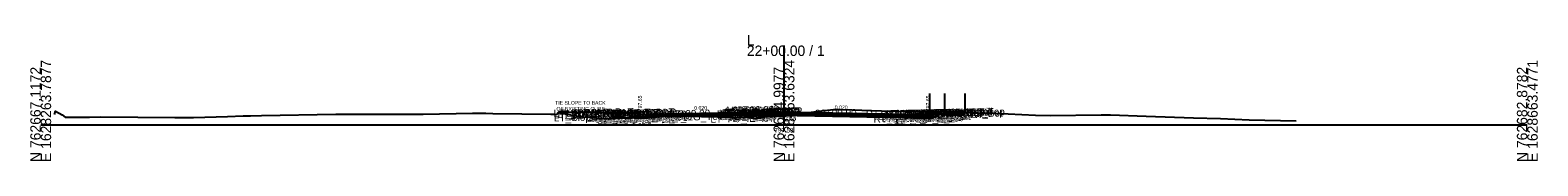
# Model space of a CAD drawing. Extents: x -26 to 4403, y -510 to 9556.
# Drawn here: x 997.2 to 1402.8, y 1990.3 to 2024.1 of the extents above; entities that cross this region are included whole.
import ezdxf

# ---------------------------------------------------------------- set-up
doc = ezdxf.new("R2010")
doc.units = 0
for name, color, linetype in [('Default', 7, 'Continuous'), ('Exist CMT Pavement', 7, 'Continuous'), ('Exist Cross Section Cell', 7, 'Continuous'), ('Exist XS Center Line Elevation Label', 7, 'Continuous'), ('Exist XS Ground Line', 7, 'Continuous'), ('Prop CMT Conc Surface', 7, 'Continuous'), ('Prop CMT Concrete Structures', 7, 'Continuous'), ('Prop CMT Pvmt Course 1', 7, 'Continuous'), ('Prop CMT Pvmt Course 1 CG', 7, 'Continuous'), ('Prop CMT Pvmt Course 1 Wedge', 7, 'Continuous'), ('Prop CMT Pvmt Course 2', 7, 'Continuous'), ('Prop CMT Pvmt Course 2 Wedge', 7, 'Continuous'), ('Prop CMT Pvmt Course 3', 7, 'Continuous'), ('Prop CMT Pvmt Course 3 Wedge', 7, 'Continuous'), ('Prop CMT Pvmt Surface', 7, 'Continuous'), ('Prop CMT Pvmt Wedge Surface 1', 7, 'Continuous'), ('Prop CMT Pvmt Wedge Surface 2', 7, 'Continuous'), ('Prop CMT Pvmt Wedge Surface 3', 7, 'Continuous'), ('Prop CMT Slope Grass', 7, 'Continuous'), ('Prop CMT Subgrade Earthwork', 7, 'Continuous'), ('Prop XS Finish Grade Concrete', 7, 'Continuous'), ('Prop XS Hydro Elevations', 7, 'Continuous'), ('Prop XS SE Text', 7, 'Continuous'), ('Prop XS Side Slope Text', 7, 'Continuous'), ('Scratch_Level_0', 7, 'Continuous'), ('Scratch_Level_1', 7, 'Continuous')]:
    doc.layers.add(name, color=color, linetype=linetype)

msp = doc.modelspace()

# ---------------------------------------------------------------- linework, layer by layer
at = {"layer": 'Exist CMT Pavement'}
msp.add_lwpolyline([(1163.27, 2002.1), (1168.97, 2002.29), (1171.48, 2002.37), (1173.53, 2002.32), (1190.76, 2001.93)], dxfattribs=at)
at = {"layer": 'Exist Cross Section Cell'}
for p, q in [((1200, 2000), (1200, 2021.33)), ((1000, 2000), (1200, 2000)), ((1200, 2000), (1400, 2000))]:
    msp.add_line(p, q, dxfattribs=at)
at = {"layer": 'Exist XS Ground Line'}
msp.add_lwpolyline([(1003.68, 2002.75), (1004, 2003.65), (1005.81, 2002.72), (1006.56, 2002.04), (1013.13, 2002.08), (1016.2, 2002.14), (1036.1, 2001.95), (1040.29, 2001.94), (1041.07, 2001.94), (1050.25, 2002.25), (1054.46, 2002.39), (1055.76, 2002.44), (1056.45, 2002.46), (1059.44, 2002.54), (1079.39, 2002.84), (1083.51, 2002.89), (1099.19, 2002.85), (1101.25, 2002.86), (1101.58, 2002.86), (1102.93, 2002.88), (1116.16, 2003.15), (1119.78, 2003.14), (1121.67, 2003.05), (1137.24, 2002.87), (1138.25, 2002.84), (1138.74, 2002.82), (1139.24, 2003.32), (1142.57, 2002.73), (1145.78, 2002.12), (1148.69, 2002.09), (1149.14, 2002.09), (1149.64, 2001.64), (1168.97, 2002.29), (1171.48, 2002.37), (1173.53, 2002.32), (1190.76, 2001.93), (1191.17, 2001.89), (1192.59, 2001.74), (1193.27, 2002.18), (1196.89, 2002.29), (1197.54, 2002.31), (1198.02, 2002.33), (1199.37, 2002.45), (1200, 2002.53), (1210.93, 2003.83), (1213.33, 2004.1), (1214.81, 2004.1), (1218.26, 2004), (1226.21, 2003.75), (1230.01, 2003.72), (1236.95, 2003.61), (1239.78, 2003.61), (1244.85, 2003.57), (1250.98, 2003.27), (1256.68, 2003.1), (1267.66, 2002.57), (1271.63, 2002.55), (1285.38, 2002.73), (1287.86, 2002.73), (1297.47, 2002.31), (1310.18, 2001.86), (1317.48, 2001.68), (1325.18, 2001.35), (1337.84, 2001.06)], dxfattribs=at)
at = {"layer": 'Prop CMT Conc Surface'}
for points in [[(1156.75, 2003.24), (1151.75, 2003.34)], [(1161.25, 2002.65), (1161.25, 2003.14), (1160.75, 2003.14)], [(1163.25, 2002.77), (1161.25, 2002.65)]]:
    msp.add_lwpolyline(points, dxfattribs=at)
at = {"layer": 'Prop CMT Concrete Structures'}
for p, q in [((1239.25, 2002.83), (1243.25, 2002.99)), ((1243.25, 2002.99), (1248.75, 2003.1)), ((1252.2, 2003.23), (1248.75, 2003.1))]:
    msp.add_line(p, q, dxfattribs=at)
for points in [[(1151.75, 2003), (1151.75, 2003.34)], [(1151.75, 2003.34), (1156.75, 2003.24)], [(1156.75, 2002.9), (1151.75, 2003)], [(1156.75, 2003.24), (1156.75, 2002.9)], [(1163.25, 2002.77), (1161.25, 2002.65), (1161.25, 2003.14), (1160.75, 2003.14)], [(1160.75, 2003.14), (1160.75, 2002.13), (1163.25, 2002.18)], [(1163.25, 2002.18), (1163.25, 2002.77)], [(1194, 2003.62), (1193.99, 2003.79), (1192.76, 2003.76), (1192.76, 2003.76), (1192.01, 2003.51), (1192, 2003.34)], [(1192, 2003.34), (1194, 2003.62)], [(1239.25, 2002.83), (1239.25, 2002.13), (1236.75, 2002.18)], [(1236.75, 2002.18), (1236.75, 2002.77)], [(1236.75, 2002.77), (1238.5, 2002.66)], [(1236.75, 2002.18), (1236.75, 2002.77)], [(1243.25, 2002.99), (1243.25, 2002.65)], [(1243.25, 2002.65), (1248.25, 2002.75)], [(1248.25, 2002.75), (1248.25, 2003.09)]]:
    msp.add_lwpolyline(points, dxfattribs=at)
at = {"layer": 'Prop CMT Pvmt Course 1'}
for points in [[(1192, 2003.34), (1163.25, 2002.77)], [(1163.25, 2002.64), (1192, 2003.21)], [(1163.25, 2002.77), (1163.25, 2002.52), (1163.25, 2002.52), (1163.25, 2002.64)], [(1192, 2003.34), (1194, 2003.62)], [(1194, 2003.37), (1192, 2003.09)], [(1192, 2003.09), (1192, 2003.34)], [(1192, 2003.09), (1192, 2003.34)], [(1192, 2003.21), (1192, 2003.09), (1192, 2003.09)], [(1194, 2003.62), (1194, 2003.37)], [(1194, 2003.62), (1236.75, 2002.77)], [(1194, 2003.37), (1194, 2003.62)], [(1236.75, 2002.52), (1194, 2003.37)], [(1194, 2003.37), (1194, 2003.37)], [(1236.75, 2002.77), (1236.75, 2002.52)]]:
    msp.add_lwpolyline(points, dxfattribs=at)
msp.add_lwpolyline([(1194, 2003.37), (1194, 2003.49), (1194, 2003.49)], close=True, dxfattribs=at)
at = {"layer": 'Prop CMT Pvmt Course 1 CG'}
for points in [[(1163.25, 2002.18), (1160.25, 2002.12), (1159.91, 2001.78)], [(1159.91, 2001.78), (1163.25, 2001.85)], [(1163.25, 2001.85), (1163.25, 2002.18)], [(1236.75, 2002.18), (1239.75, 2002.12), (1240.09, 2001.78)], [(1236.75, 2001.85), (1236.75, 2002.18)], [(1240.09, 2001.78), (1236.75, 2001.85)]]:
    msp.add_lwpolyline(points, dxfattribs=at)
at = {"layer": 'Prop CMT Pvmt Course 1 Wedge'}
for points in [[(1163.25, 2002.64), (1168.97, 2002.75), (1171.48, 2002.8), (1173.53, 2002.85), (1190.76, 2003.19), (1191.17, 2003.2), (1192, 2003.21)], [(1192, 2003.09), (1191.17, 2003.07), (1190.76, 2003.07), (1173.53, 2002.72), (1171.48, 2002.68), (1168.97, 2002.63), (1163.25, 2002.52)], [(1163.25, 2002.52), (1163.25, 2002.64)], [(1192, 2003.21), (1192, 2003.09)]]:
    msp.add_lwpolyline(points, dxfattribs=at)
at = {"layer": 'Prop CMT Pvmt Course 2'}
for points in [[(1163.25, 2002.18), (1163.25, 2002.18), (1163.25, 2002.52), (1163.25, 2002.52)], [(1163.25, 2002.52), (1163.25, 2002.18)], [(1192, 2003.09), (1194, 2003.37)], [(1192, 2002.76), (1192, 2003.09)], [(1194, 2003.04), (1192, 2002.76)], [(1194, 2003.37), (1194, 2003.04)], [(1194, 2003.04), (1194, 2003.37)], [(1194, 2003.37), (1236.75, 2002.52)], [(1236.75, 2002.18), (1194, 2003.04)], [(1236.75, 2002.52), (1236.75, 2002.18)]]:
    msp.add_lwpolyline(points, dxfattribs=at)
at = {"layer": 'Prop CMT Pvmt Course 2 Wedge'}
for points in [[(1163.25, 2002.52), (1168.97, 2002.63), (1171.48, 2002.68), (1173.53, 2002.72), (1190.76, 2003.07), (1191.17, 2003.07), (1192, 2003.09)], [(1192, 2002.76), (1191.17, 2002.74), (1190.76, 2002.73), (1173.53, 2002.39), (1172.1, 2002.36), (1171.48, 2002.37), (1169.69, 2002.31), (1168.97, 2002.3), (1163.25, 2002.18)], [(1163.25, 2002.18), (1163.25, 2002.52)], [(1192, 2003.09), (1192, 2002.76)]]:
    msp.add_lwpolyline(points, dxfattribs=at)
at = {"layer": 'Prop CMT Pvmt Course 3'}
for points in [[(1163.25, 2002.18), (1163.25, 2002.18), (1163.25, 2001.85), (1163.25, 2001.85)], [(1163.25, 2001.85), (1163.25, 2002.18)], [(1192, 2002.76), (1194, 2003.04)], [(1192, 2002.42), (1192, 2002.76)], [(1194, 2002.7), (1192, 2002.42)], [(1194, 2003.04), (1194, 2002.7)], [(1194, 2003.04), (1236.75, 2002.18)], [(1194, 2002.7), (1194, 2003.04)], [(1236.75, 2001.85), (1194, 2002.7)], [(1236.75, 2002.18), (1236.75, 2001.85)]]:
    msp.add_lwpolyline(points, dxfattribs=at)
at = {"layer": 'Prop CMT Pvmt Course 3 Wedge'}
for points in [[(1163.25, 2002.18), (1168.97, 2002.3), (1169.71, 2002.31)], [(1169.71, 2002.31), (1168.97, 2002.29), (1163.25, 2002.1)], [(1163.25, 2002.1), (1163.25, 2002.18)], [(1172.09, 2002.36), (1173.53, 2002.39)], [(1192, 2001.8), (1191.17, 2001.89), (1190.76, 2001.93), (1173.53, 2002.32), (1172.09, 2002.36)], [(1173.53, 2002.39), (1190.76, 2002.73), (1191.17, 2002.74), (1192, 2002.76)]]:
    msp.add_lwpolyline(points, dxfattribs=at)
at = {"layer": 'Prop CMT Pvmt Surface'}
for points in [[(1192, 2003.34), (1163.25, 2002.77)], [(1192, 2003.34), (1194, 2003.62)], [(1194, 2003.62), (1236.75, 2002.77)]]:
    msp.add_lwpolyline(points, dxfattribs=at)
at = {"layer": 'Prop CMT Pvmt Wedge Surface 1'}
for points in [[(1192, 2003.21), (1163.25, 2002.64)], [(1163.25, 2002.52), (1163.25, 2002.77)], [(1163.25, 2002.64), (1163.25, 2002.52), (1163.25, 2002.52)], [(1192, 2003.34), (1192, 2003.09), (1192, 2003.09), (1192, 2003.21)]]:
    msp.add_lwpolyline(points, dxfattribs=at)
at = {"layer": 'Prop CMT Pvmt Wedge Surface 2'}
for points in [[(1192, 2003.09), (1163.25, 2002.52)], [(1163.25, 2002.52), (1163.25, 2002.77)], [(1192, 2003.34), (1192, 2003.09)]]:
    msp.add_lwpolyline(points, dxfattribs=at)
at = {"layer": 'Prop CMT Pvmt Wedge Surface 3'}
for points in [[(1163.25, 2002.18), (1163.25, 2002.77)], [(1192, 2002.76), (1163.25, 2002.18)], [(1192, 2003.34), (1192, 2002.76)]]:
    msp.add_lwpolyline(points, dxfattribs=at)
at = {"layer": 'Prop CMT Slope Grass'}
msp.add_lwpolyline([(1160.75, 2003.14), (1151.25, 2003.34), (1139.24, 2003.32)], dxfattribs=at)
at = {"layer": 'Prop CMT Subgrade Earthwork'}
msp.add_line((1190.76, 2002.4), (1190.76, 2001.93), dxfattribs=at)
for points in [[(1163.25, 2001.85), (1159.91, 2001.78), (1158.5, 2003.19)], [(1163.25, 2001.85), (1163.27, 2002.1)], [(1163.25, 2001.85), (1163.25, 2001.85)], [(1192, 2002.42), (1191.17, 2002.41), (1190.76, 2002.4)], [(1192, 2002.42), (1194, 2002.7)], [(1194, 2002.7), (1236.75, 2001.85)], [(1236.75, 2001.85), (1240.09, 2001.78), (1241.21, 2002.91)]]:
    msp.add_lwpolyline(points, dxfattribs=at)
at = {"layer": 'Prop XS Finish Grade Concrete'}
msp.add_line((1238.5, 2002.66), (1239.25, 2002.83), dxfattribs=at)
at = {"layer": 'Scratch_Level_1'}
for p, q in [((1239.25, 2002.83), (1239.25, 2008.47)), ((1243.25, 2002.99), (1243.25, 2008.47)), ((1248.75, 2003.1), (1248.75, 2008.47))]:
    msp.add_line(p, q, dxfattribs=at)

# ---------------------------------------------------------------- texts
at = {"layer": 'Default'}
msp.add_text('-', height=0.0001, dxfattribs=at).set_placement((1000, 2000))
at = {"layer": 'Exist Cross Section Cell'}
for s, p in [('22+00.00 / 1', (1190, 2018.53)), ('L', (1190, 2021.33))]:
    msp.add_text(s, height=2.8, dxfattribs=at).set_placement(p)
for s, p in [('E 1628263.7877', (1002.8, 1990)), ('E 1628463.6324', (1202.8, 1990)), ('E 1628663.4771', (1402.8, 1990)), ('N 762667.1172', (1000, 1990)), ('N 762674.9977', (1200, 1990)), ('N 762682.8782', (1400, 1990))]:
    msp.add_text(s, height=2.8, rotation=90, dxfattribs=at).set_placement(p)
at = {"layer": 'Exist XS Center Line Elevation Label'}
msp.add_text('797.53', height=1.2, dxfattribs=at).set_placement((1197.46, 1997.93))
at = {"layer": 'Prop XS Hydro Elevations'}
for p in [(1161.75, 2003.65), (1239.25, 2003.65)]:
    msp.add_text('797.65', height=1, rotation=90, dxfattribs=at).set_placement(p)
at = {"layer": 'Prop XS SE Text'}
for s, rotation, p in [('0.020', 1.1457, (1175.86, 2004.02)), ('0.020', 358.8543, (1213.65, 2004.23)), ('4.00%', 2.2906, (1239.43, 2003.15)), ('2.00%', 1.1458, (1244.19, 2003.19)), ('4.00%', 2.2906, (1249.04, 2003.32))]:
    msp.add_text(s, height=1, rotation=rotation, dxfattribs=at).set_placement(p)
at = {"layer": 'Prop XS Side Slope Text'}
for s, p in [('TIE SLOPE TO BACK', (1138.42, 2005.42)), ('OF EXISTING CURB', (1138.78, 2003.79))]:
    msp.add_text(s, height=1, dxfattribs=at).set_placement(p)
at = {"layer": 'Scratch_Level_0'}
for s, p in [('LT_SDWK_Out_Top', (1138.01, 2002.06)), ('LT_SDWK_Out_Bot', (1138.04, 2001.73)), ('LT_Sub_Trench_Out_DLT', (1139.09, 2001.8)), ('LT_CSLP_Pnt', (1141.44, 2002.14)), ('LT_SDWK_In_Top', (1144.63, 2001.99)), ('LT_CG_Top_Face', (1148.53, 2001.89)), ('LT_CG_Top_BOC', (1149.05, 2001.91)), ('22+00.00', (1153.57, 2002.02)), ('22+00.00', (1154.1, 2002.01)), ('22+00.00', (1168.94, 2001.88)), ('LT_PV2_IEEOP', (1181.98, 2001.89)), ('LT_PV1_IEEOP', (1182.54, 2002.03)), ('LT_PV2_PGL1', (1182.9, 2001.91)), ('LT_PV2_PGL', (1183.23, 2001.91)), ('RT_PV2_OEEOP', (1183.28, 2002.16)), ('RT_PV3_OEEOP', (1183.28, 2001.82)), ('LT_PV1_PGL', (1183.8, 2002.18)), ('RT_PV1_OEEOP', (1183.85, 2002.29)), ('MI_Face In', (1183.92, 2002.35)), ('RT_PV2_IEEOP', (1183.93, 2002.17)), ('MI_Face Out', (1184.28, 2002.59)), ('MI_Top Out', (1184.49, 2002.86)), ('RT_PV1_IEEOP', (1184.49, 2002.3)), ('RT_PV2_PGL1', (1184.86, 2002.19)), ('RT_PV3_PGL1', (1184.86, 2001.85)), ('22+00.00', (1185.19, 2002.33)), ('RT_PV2_PGL', (1185.19, 2002.19)), ('MI_Bot Out', (1185.28, 2002.45)), ('22+00.00', (1185.38, 2002.43)), ('MI_Top In', (1185.63, 2002.61)), ('RT_PV1_PGL', (1185.75, 2002.45)), ('22+00.00', (1186.13, 2002.83)), ('MI_Crown', (1186.09, 2002.9)), ('22+00.00', (1186.26, 2002.9)), ('22+00.00', (1186.96, 2002.72)), ('22+00.00', (1187.18, 2002.59)), ('22+00.00', (1208.33, 2002.06)), ('RT_Sub_Trench_Out_DLT', (1222.04, 2001.8)), ('RT_CG_Top_Face', (1225.99, 2001.89)), ('RT_CG_Top_BOC', (1227.51, 2001.91)), ('RT_SDWK_In_Top', (1231.08, 2001.99)), ('22+00.00', (1232.24, 2002.01)), ('22+00.00', (1233.87, 2002.04)), ('RT_SDWK_Out_Top', (1234.46, 2002.06)), ('RT_SDWK_Out_Bot', (1234.49, 2001.73)), ('RT_Slope_Cut', (1238.48, 2002.17)), ('RT_Slope_Fill', (1239.36, 2002.18)), ('RT_Shld_O', (1240.81, 2002.18)), ('CSLP_Pnt', (1241.64, 2002.19)), ('22+00.00', (1242.01, 2002.22)), ('LT_Slope_Fill', (1138.1, 2000.91)), ('22+00.00', (1142.56, 2001.57)), ('LT_SDWK_In_Bot', (1144.66, 2001.66)), ('LT_CG1_Shelf_Out', (1146.82, 2000.85)), ('LT_PV_Sub_Tie_Out', (1148.23, 2000.8)), ('LT_CG_Bot_BOC', (1149.09, 2000.9)), ('LT_CG_Top_Gut', (1149.51, 2001.41)), ('LT_Sub_OEOP', (1150.04, 2000.58)), ('LT_Sub_OEOT_CG', (1150.64, 2000.6)), ('LT_PV_OEEOP_EG', (1150.82, 2000.85)), ('LT_Sub_OEEOP', (1152.48, 2000.63)), ('LT_PV2_OEEOP', (1152.58, 2001.3)), ('LT_PV3_OEEOP', (1152.58, 2000.97)), ('LT_PV1_OEEOP', (1153.15, 2001.44)), ('LT_CG_Bot_IE', (1153.19, 2000.98)), ('LT_Sub_OEOT', (1153.35, 2000.65)), ('LT_PV2_OEOT', (1153.45, 2001.32)), ('LT_PV3_OEOT', (1153.45, 2000.99)), ('LT_PV1_OEOT', (1154.01, 2001.58)), ('LT_PV_EG_TestPt', (1164.06, 2000.96)), ('LT_PV_IEEOP_EG', (1180.21, 2000.56)), ('LT_PV3_IEEOP', (1181.98, 2001.56)), ('LT_PV3_PGL1', (1182.9, 2001.57)), ('RT_Sub_OEEOP', (1183.19, 2001.49)), ('LT_PV3_PGL', (1183.23, 2001.58)), ('LT_PV4_PGL', (1183.23, 2001.25)), ('RT_PV4_PGL', (1185.19, 2001.53)), ('RT_Sub_OEOT_CG', (1224.1, 2000.59)), ('RT_CG1_Shelf_Out', (1226.28, 2000.85)), ('RT_CG_Bot_IE', (1226.64, 2000.98)), ('RT_Sub_OEOT', (1226.8, 2000.65)), ('RT_PV2_OEOT', (1226.9, 2001.32)), ('RT_PV3_OEOT', (1226.9, 2000.98)), ('RT_CG_Top_Gut', (1226.96, 2001.41)), ('RT_PV1_OEOT', (1227.46, 2001.58)), ('RT_CG_Bot_BOC', (1227.54, 2000.9)), ('RT_Sub_OEOP', (1230.17, 2000.58)), ('RT_SDWK_In_Bot', (1231.12, 2001.66))]:
    msp.add_text(s, height=2, rotation=1.1458, dxfattribs=at).set_placement(p)

doc.saveas('drawing.dxf')
